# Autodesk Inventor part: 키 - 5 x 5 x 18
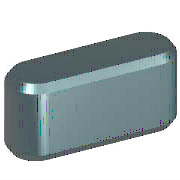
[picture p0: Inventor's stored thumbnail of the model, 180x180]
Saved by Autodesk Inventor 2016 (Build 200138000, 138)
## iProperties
Created: 2012-02
Part Number: 키 - 5 x 5 x 18
Material: 강철, 연강
Description: 키 및 해당 키홈
Document SubType Name: Modeling
Standard: KS B 1311
Designer: mduedu
Standards Organization: KS
Language: ko-KR
Size Designation: 5 x 5 x 18
Categories: <MemberInstance><Categories><Category DisplayName="샤프트 부품" InternalName="7f7aeb1f-a693-4053-b835-cee3144e0d98" Mnemonic="SHFT"><Category DisplayName="키" Interna
Density: 7.85 g/cm^3
Appearance: 매끄러움 - 노란색
Mass: 3.27059 g
Surface Area: 3.57848 cm^2
Volume: 0.416636 cm^3
IsCustomPart: 1
Author: mduedu
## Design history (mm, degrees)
workplane "Work Plane1"
workplane "Work Plane2"
sketch "스케치1"
  geometry: L1 (2.5, 2.5)-(15.5, 2.5); L2 (15.5, -2.5)-(2.5, -2.5); L3 (0, 9.4)-(0, -7.4) reference; L4 (-5, 0)-(30, 0) reference; L5 (18, 0)-(18, 7); A1 r 2.5 centre (2.5, 0) between (2.5, 2.5) and (2.5, -2.5); A2 r 2.5 centre (15.5, 0) between (15.5, -2.5) and (15.5, 2.5)
  constraints: 6 end point, 5 point on circle, 4 tangent, 3 point on line, 2 centre point, 1 horizontal, 1 parallel, 1 perpendicular
  dimensions: "d0" = 2.5 radius of A1 (= 0.5 x PB); "d13" = 2.5 radius of A2 (= 0.5 x PB); "d14" = 18 distance between parallel lines of L5 L3 (= NLG)
extrude "본체1" new body sketch "스케치1" taper "d3" = 0 deg; stored distance "d4" = 10
workplane "Work Plane3"
body "Solid1"
chamfer "모따기1" distance "d8" = 0.4 (= PHH); stored, may be unused: second distance "d9" = 0.4 (= PHH), angle "d15" = 45 deg
other parameters: "d1" = -3 (= -PNT), "d2" = 2 (= PH - PNT), "NLG" = 18 [user parameter; used in 3 equation terms], "PB" = 5 [user parameter; used in 2 equation terms], "PNT" = 3 [user parameter; used in 2 equation terms], "PH" = 5 [user parameter; used in 1 equation term], "PHH" = 0.4 [user parameter; used in 2 equation terms], "d10" = 0, "d16" = 0, "d17" = 0, "d18" = 0, "WDMIN" = 12 [user parameter], "PLB2" = 18 (= NLG) [user parameter], "WDMAX" = 17 [user parameter], "PLB1" = 18 (= NLG) [user parameter], "RR" = 0.16 [user parameter], "PUEB" = 2.3 [user parameter]
